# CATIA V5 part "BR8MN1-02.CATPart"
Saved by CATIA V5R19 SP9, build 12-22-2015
Part number: BR8MN1-02
Definition: design
Nomenclature: BR8MN1-02
Source: Unknown
Bounding box of the stored display mesh (mm): x -4.6 to 7.9, y 0 to 12, z 0 to 10.16
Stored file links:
  Z:\charly_robot\BR8MN1-02.CATPart
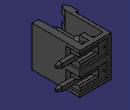
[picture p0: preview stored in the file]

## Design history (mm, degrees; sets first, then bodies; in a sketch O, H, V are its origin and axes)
AxisSystem1: origin (0, 0, 0), X (1, 0, 0), Y (0, 1, 0), Z (0, 0, 1)
Body1 "MANIFOLD_SOLID_BREP #164119" (main body)
  Solid1: solid without history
